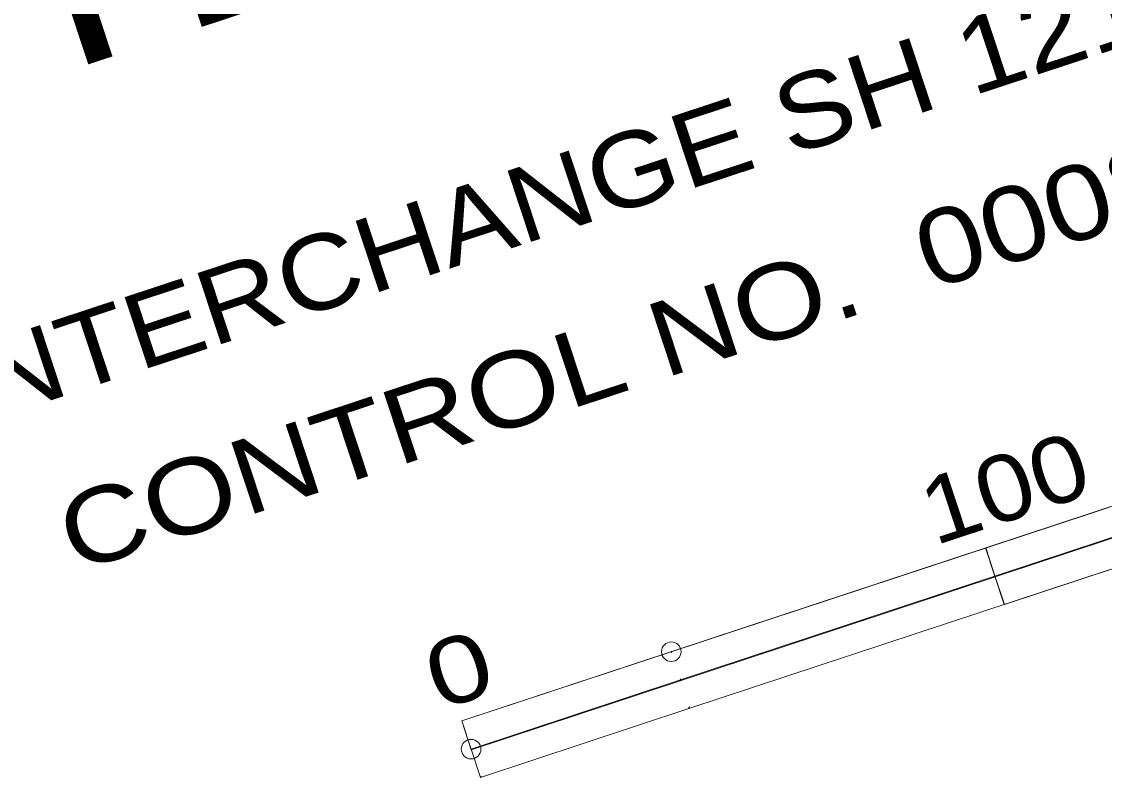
# Model space of a CAD drawing. Extents: x 2355803 to 2371254, y 6970215 to 6985302.
# Drawn here: x 2370614.5 to 2370810.7, y 6978506.9 to 6978644 of the extents above; entities that cross this region are included whole.
import ezdxf

# ---------------------------------------------------------------- set-up
doc = ezdxf.new("R2010")
doc.units = 0
doc.header["$LTSCALE"] = 7.1
doc.header["$PDMODE"] = 32
doc.header["$PDSIZE"] = 3.55
doc.layers.add('19', color=7, linetype='Continuous', lineweight=13)
doc.layers.add('8', color=7, linetype='Continuous', lineweight=13)

msp = doc.modelspace()

# ---------------------------------------------------------------- linework, layer by layer
at = {"layer": '19'}
for p, q in [((2370694.245, 6978517.12), (2370884.153, 6978579.858)), ((2370808.19, 6978554.762), (2370884.153, 6978579.858)), ((2370732.227, 6978529.668), (2370808.19, 6978554.762)), ((2370808.148, 6978554.748), (2370808.204, 6978554.72)), ((2370809.881, 6978549.641), (2370733.919, 6978524.546)), ((2370789.199, 6978548.489), (2370792.583, 6978538.246)), ((2370735.611, 6978519.425), (2370811.573, 6978544.519)), ((2370694.245, 6978517.12), (2370732.227, 6978529.668)), ((2370732.256, 6978529.582), (2370732.313, 6978529.696)), ((2370732.285, 6978529.493), (2370732.402, 6978529.725)), ((2370695.938, 6978511.999), (2370733.919, 6978524.546)), ((2370733.759, 6978524.493), (2370733.973, 6978524.386)), ((2370733.847, 6978524.523), (2370733.942, 6978524.475)), ((2370733.852, 6978524.749), (2370734.122, 6978524.613)), ((2370733.881, 6978524.66), (2370734.032, 6978524.584)), ((2370733.911, 6978524.571), (2370733.943, 6978524.554)), ((2370735.289, 6978519.318), (2370735.505, 6978519.747)), ((2370735.378, 6978519.348), (2370735.534, 6978519.657)), ((2370695.938, 6978511.999), (2370694.245, 6978517.12)), ((2370695.963, 6978511.921), (2370696.016, 6978512.024)), ((2370695.994, 6978511.831), (2370696.105, 6978512.054)), ((2370697.55, 6978507.117), (2370697.869, 6978506.956)), ((2370697.58, 6978507.027), (2370697.779, 6978506.927))]:
    msp.add_line(p, q, dxfattribs=at)
for points in [[(2370790.946, 6978543.264), (2370885.881, 6978574.626), (2370887.537, 6978569.614), (2370792.601, 6978538.252)], [(2370694.245, 6978517.12), (2370789.218, 6978548.495), (2370790.946, 6978543.264), (2370695.973, 6978511.89)]]:
    msp.add_lwpolyline(points, close=True, dxfattribs=at)
for points in [[(2370809.881, 6978549.641), (2370885.845, 6978574.736), (2370887.537, 6978569.614)], [(2370735.611, 6978519.425), (2370697.629, 6978506.877), (2370695.938, 6978511.999)]]:
    msp.add_lwpolyline(points, dxfattribs=at)
for p in [(2370732.227, 6978529.668), (2370695.938, 6978511.999)]:
    msp.add_point(p, dxfattribs=at)
at = {"layer": '8'}
for p, q in [((2370694.245, 6978517.12), (2370884.153, 6978579.858)), ((2370808.19, 6978554.762), (2370884.153, 6978579.858)), ((2370732.227, 6978529.668), (2370808.19, 6978554.762)), ((2370808.148, 6978554.748), (2370808.204, 6978554.72)), ((2370809.881, 6978549.641), (2370733.919, 6978524.546)), ((2370789.199, 6978548.489), (2370792.583, 6978538.246)), ((2370735.611, 6978519.425), (2370811.573, 6978544.519)), ((2370694.245, 6978517.12), (2370732.227, 6978529.668)), ((2370732.256, 6978529.582), (2370732.313, 6978529.696)), ((2370732.285, 6978529.493), (2370732.402, 6978529.725)), ((2370695.938, 6978511.999), (2370733.919, 6978524.546)), ((2370733.759, 6978524.493), (2370733.973, 6978524.386)), ((2370733.847, 6978524.523), (2370733.942, 6978524.475)), ((2370733.852, 6978524.749), (2370734.122, 6978524.613)), ((2370733.881, 6978524.66), (2370734.032, 6978524.584)), ((2370733.911, 6978524.571), (2370733.943, 6978524.554)), ((2370735.289, 6978519.318), (2370735.505, 6978519.747)), ((2370735.378, 6978519.348), (2370735.534, 6978519.657)), ((2370695.938, 6978511.999), (2370694.245, 6978517.12)), ((2370695.963, 6978511.921), (2370696.016, 6978512.024)), ((2370695.994, 6978511.831), (2370696.105, 6978512.054)), ((2370697.55, 6978507.117), (2370697.869, 6978506.956)), ((2370697.58, 6978507.027), (2370697.779, 6978506.927))]:
    msp.add_line(p, q, dxfattribs=at)
for points in [[(2370790.946, 6978543.264), (2370885.881, 6978574.626), (2370887.537, 6978569.614), (2370792.601, 6978538.252)], [(2370694.245, 6978517.12), (2370789.218, 6978548.495), (2370790.946, 6978543.264), (2370695.973, 6978511.89)]]:
    msp.add_lwpolyline(points, close=True, dxfattribs=at)
for points in [[(2370809.881, 6978549.641), (2370885.845, 6978574.736), (2370887.537, 6978569.614)], [(2370735.611, 6978519.425), (2370697.629, 6978506.877), (2370695.938, 6978511.999)]]:
    msp.add_lwpolyline(points, dxfattribs=at)
for p in [(2370732.227, 6978529.668), (2370695.938, 6978511.999)]:
    msp.add_point(p, dxfattribs=at)

# ---------------------------------------------------------------- texts
at = {"layer": '19'}
for s, height, width, p in [(' HOV ALTERNATIVE 5A', 23.33, 1.6, (2370427.262, 6978570.366)), ('LIMITS:  NORTH INTERCHANGE SH 121 TO RANDOL MILL ROAD', 13.58, 1.15, (2370447.402, 6978518.316)), ('CONTROL NO.  0008-13-123', 13.58, 1.2, (2370624.026, 6978543.906)), ('100', 12, 1.15, (2370779.929, 6978548.872)), ('0', 12, 1.3, (2370690.124, 6978518.961))]:
    msp.add_text(s, height=height, rotation=18.281, dxfattribs=dict(at, width=width)).set_placement(p)
at = {"layer": '8'}
for s, height, width, p in [(' HOV ALTERNATIVE 5A', 23.33, 1.6, (2370427.262, 6978570.366)), ('LIMITS:  NORTH INTERCHANGE SH 121 TO RANDOL MILL ROAD', 13.58, 1.15, (2370447.402, 6978518.316)), ('CONTROL NO.  0008-13-123', 13.58, 1.2, (2370624.026, 6978543.906)), ('100', 12, 1.15, (2370779.929, 6978548.872)), ('0', 12, 1.3, (2370690.124, 6978518.961))]:
    msp.add_text(s, height=height, rotation=18.281, dxfattribs=dict(at, width=width)).set_placement(p)

doc.saveas('drawing.dxf')
